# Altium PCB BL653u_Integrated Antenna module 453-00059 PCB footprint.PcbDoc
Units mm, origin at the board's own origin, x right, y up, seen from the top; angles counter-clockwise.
Board outline 8.6 x 6.3 mm, 2 copper layers (Top Layer, Bottom Layer); 1 components, 0 nets, 59 pads, 0 vias.
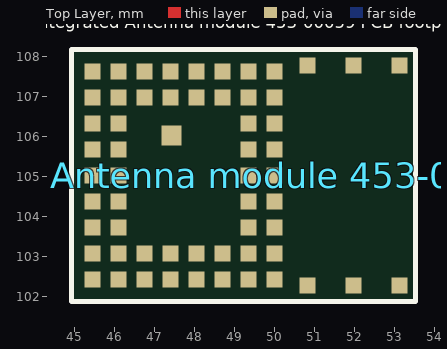
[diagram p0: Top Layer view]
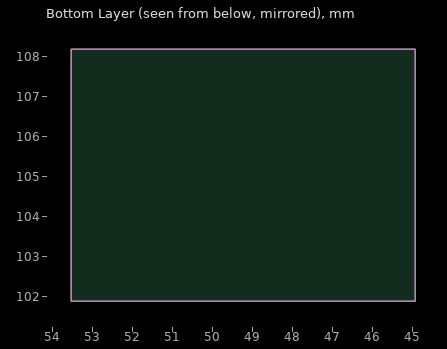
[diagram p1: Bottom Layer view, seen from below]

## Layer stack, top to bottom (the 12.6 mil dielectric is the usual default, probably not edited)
Top Solder: solder mask 0.0102, Solder Resist, Dk 3.5
Top Layer: signal copper 0.0356
Dielectric 1: dielectric 0.32, FR-4, Dk 4.8
Bottom Layer: signal copper 0.0356
Bottom Solder: solder mask 0.0102, Solder Resist, Dk 3.5

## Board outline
44.913,101.879 53.514,101.879 53.514,108.179 44.913,108.179

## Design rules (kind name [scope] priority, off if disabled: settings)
Clearance [All] p1: gap=0.254 ignorepadtopadclearanceinfootprint=FALSE except(0: Arc-Hole Track-Hole SMDPad-Hole THPad-Hole Via-Hole Fill-Hole Poly-Hole Region-Hole Text-Hole)
PolygonConnect [All] p1: connectstyle=Relief reliefconductorwidth=0.254 reliefentries=4 polygonreliefangle="90 Angle" airgapwidth=0.254
RoutingVias [All] p1: holewidth=0.711 width=1.27 viastyle="Through Hole" minholewidth=0.711 minwidth=1.27 maxholewidth=0.711 maxwidth=1.27
SolderMaskExpansion [All] p1: expansion=0.102
Width [All] p1: maxlimit=0.254 minlimit=0.254 preferedwidth=0.254
30 further rules are at their usual default settings.

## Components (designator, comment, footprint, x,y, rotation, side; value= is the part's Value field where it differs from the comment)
"BL653u_Integrated Antenna module 453-00059 PCB footprint" "Comment" "LAIRD, BL653U_SA_MODULE" 49.276,105.029 r0 top

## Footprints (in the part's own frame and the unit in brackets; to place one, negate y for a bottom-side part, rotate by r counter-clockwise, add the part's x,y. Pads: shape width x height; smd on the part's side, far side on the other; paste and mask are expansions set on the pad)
"LAIRD, BL653U_SA_MODULE" [mm] "Laird, BL653 Module_SA"
  rect 0.4x0.4 smd mask+0.051: 1(0.712,2.6) 2(0.712,1.95) 3(0.712,1.3) 4(0.712,0.65) 5(0.712,0) 6(0.712,-0.65) 7(0.712,-1.3) 8(0.712,-1.95) 9(0.712,-2.6) 10(0.062,-2.6) 11(-0.587,-2.6) 12(-1.237,-2.6) 13(-1.887,-2.6) 14(-2.537,-2.6) 15(-3.187,-2.6) 16(-3.837,-2.6) 17(-3.837,-1.95) 18(-3.837,-1.3) 19(-3.837,-0.65) 20(-3.837,0) 21(-3.837,0.65) 22(-3.837,1.3) 23(-3.837,1.95) 24(-3.837,2.6) 25(-3.187,2.6) 26(-2.537,2.6) 27(-1.887,2.6) 28(-1.237,2.6) 29(-0.588,2.6) 30(0.063,2.6) 31(0.062,1.95) 32(0.062,1.3) 33(0.062,0.65) 34(0.062,0) 35(0.062,-0.65) 36(0.062,-1.3) 37(0.063,-1.95) 38(-0.588,-1.95) 39(-1.237,-1.95) 40(-1.887,-1.95) 41(-2.537,-1.95) 42(-3.187,-1.95) 43(-3.187,-1.3) 44(-3.187,-0.65) 45(-3.187,0) 46(-3.187,0.65) 47(-3.187,1.3) 48(-3.187,1.95) 49(-2.537,1.95) 50(-1.887,1.95) 51(-1.237,1.95) 52(-0.587,1.95) G2(3.837,-2.75) G3(2.687,-2.75) G4(1.537,-2.75) G5(1.538,2.75) G6(2.687,2.75) G7(3.837,2.75)
  rect 0.5x0.5 smd mask+0.051: G1(-1.862,1)
  silkscreen extent -4.36,-3.15 4.24,3.15, body extent -4.04,-2.95 4.04,2.95, height 0.01

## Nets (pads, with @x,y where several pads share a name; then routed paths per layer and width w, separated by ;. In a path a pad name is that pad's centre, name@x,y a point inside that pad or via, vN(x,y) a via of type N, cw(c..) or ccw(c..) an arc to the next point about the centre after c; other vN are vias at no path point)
pads on no net: "BL653u_Integrated Antenna module 453-00059 PCB footprint.1" "BL653u_Integrated Antenna module 453-00059 PCB footprint.2" "BL653u_Integrated Antenna module 453-00059 PCB footprint.3" "BL653u_Integrated Antenna module 453-00059 PCB footprint.4" "BL653u_Integrated Antenna module 453-00059 PCB footprint.5" "BL653u_Integrated Antenna module 453-00059 PCB footprint.6" "BL653u_Integrated Antenna module 453-00059 PCB footprint.7" "BL653u_Integrated Antenna module 453-00059 PCB footprint.8" "BL653u_Integrated Antenna module 453-00059 PCB footprint.9" "BL653u_Integrated Antenna module 453-00059 PCB footprint.10" "BL653u_Integrated Antenna module 453-00059 PCB footprint.11" "BL653u_Integrated Antenna module 453-00059 PCB footprint.12" "BL653u_Integrated Antenna module 453-00059 PCB footprint.13" "BL653u_Integrated Antenna module 453-00059 PCB footprint.14" "BL653u_Integrated Antenna module 453-00059 PCB footprint.15" "BL653u_Integrated Antenna module 453-00059 PCB footprint.16" "BL653u_Integrated Antenna module 453-00059 PCB footprint.17" "BL653u_Integrated Antenna module 453-00059 PCB footprint.18" "BL653u_Integrated Antenna module 453-00059 PCB footprint.19" "BL653u_Integrated Antenna module 453-00059 PCB footprint.20" "BL653u_Integrated Antenna module 453-00059 PCB footprint.21" "BL653u_Integrated Antenna module 453-00059 PCB footprint.22" "BL653u_Integrated Antenna module 453-00059 PCB footprint.23" "BL653u_Integrated Antenna module 453-00059 PCB footprint.24" "BL653u_Integrated Antenna module 453-00059 PCB footprint.25" "BL653u_Integrated Antenna module 453-00059 PCB footprint.26" "BL653u_Integrated Antenna module 453-00059 PCB footprint.27" "BL653u_Integrated Antenna module 453-00059 PCB footprint.28" "BL653u_Integrated Antenna module 453-00059 PCB footprint.29" "BL653u_Integrated Antenna module 453-00059 PCB footprint.30" "BL653u_Integrated Antenna module 453-00059 PCB footprint.31" "BL653u_Integrated Antenna module 453-00059 PCB footprint.32" "BL653u_Integrated Antenna module 453-00059 PCB footprint.33" "BL653u_Integrated Antenna module 453-00059 PCB footprint.34" "BL653u_Integrated Antenna module 453-00059 PCB footprint.35" "BL653u_Integrated Antenna module 453-00059 PCB footprint.36" "BL653u_Integrated Antenna module 453-00059 PCB footprint.37" "BL653u_Integrated Antenna module 453-00059 PCB footprint.38" "BL653u_Integrated Antenna module 453-00059 PCB footprint.39" "BL653u_Integrated Antenna module 453-00059 PCB footprint.40" "BL653u_Integrated Antenna module 453-00059 PCB footprint.41" "BL653u_Integrated Antenna module 453-00059 PCB footprint.42" "BL653u_Integrated Antenna module 453-00059 PCB footprint.43" "BL653u_Integrated Antenna module 453-00059 PCB footprint.44" "BL653u_Integrated Antenna module 453-00059 PCB footprint.45" "BL653u_Integrated Antenna module 453-00059 PCB footprint.46" "BL653u_Integrated Antenna module 453-00059 PCB footprint.47" "BL653u_Integrated Antenna module 453-00059 PCB footprint.48" "BL653u_Integrated Antenna module 453-00059 PCB footprint.49" "BL653u_Integrated Antenna module 453-00059 PCB footprint.50" "BL653u_Integrated Antenna module 453-00059 PCB footprint.51" "BL653u_Integrated Antenna module 453-00059 PCB footprint.52" "BL653u_Integrated Antenna module 453-00059 PCB footprint.G1" "BL653u_Integrated Antenna module 453-00059 PCB footprint.G2" "BL653u_Integrated Antenna module 453-00059 PCB footprint.G3" "BL653u_Integrated Antenna module 453-00059 PCB footprint.G4" "BL653u_Integrated Antenna module 453-00059 PCB footprint.G5" "BL653u_Integrated Antenna module 453-00059 PCB footprint.G6" "BL653u_Integrated Antenna module 453-00059 PCB footprint.G7"

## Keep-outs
Keep-Out Layer:
  the board outline again, w0.025

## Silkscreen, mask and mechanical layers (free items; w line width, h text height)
Mechanical 1:
  lines w0.025: 53.513,102.529 50.513,102.529 50.513,107.529 53.513,107.529 ; 53.514,102.529 53.514,107.529
  text "Keep out  / Area" at 51.181,106.553 h0.51 r270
